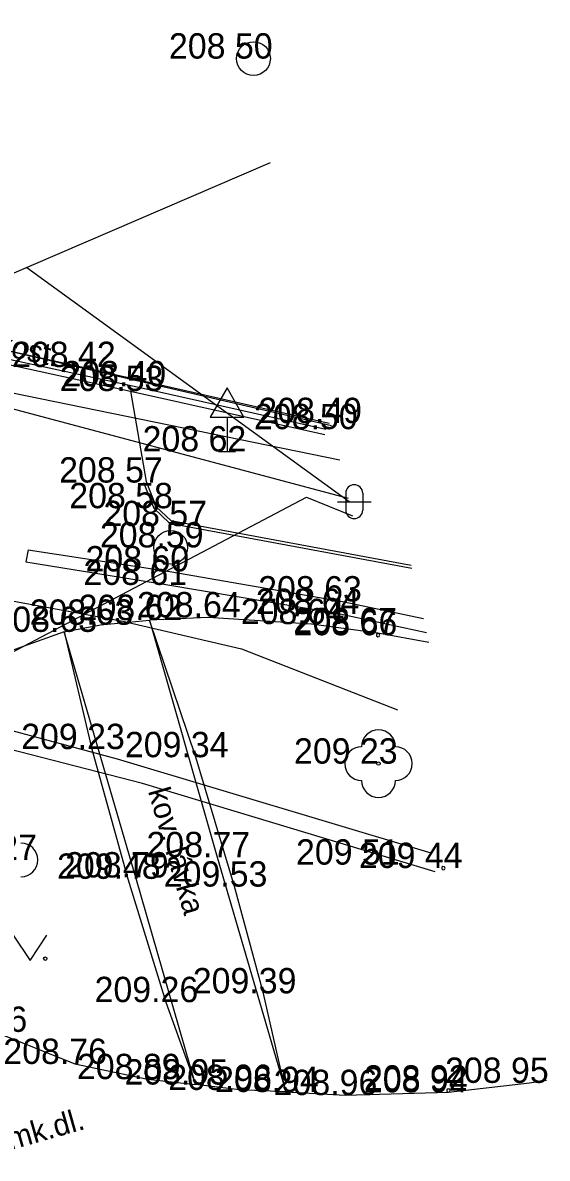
# Model space of a CAD drawing. Extents: x -524633 to -524336, y -1187893 to -1187683.
# Drawn here: x -524498.44 to -524482.91, y -1187763.42 to -1187729.81 of the extents above; entities that cross this region are included whole.
import ezdxf

# ---------------------------------------------------------------- set-up
doc = ezdxf.new("R2010")
doc.units = 0
for name, color, linetype in [('Hranice parcel', 7, 'Continuous'), ('Vrstva 1', 7, 'Continuous'), ('Vrstva 10', 7, 'Continuous'), ('Vrstva 11', 7, 'Continuous'), ('Vrstva 22', 7, 'Continuous'), ('Vrstva 27', 7, 'Continuous'), ('Vrstva 3', 7, 'Continuous'), ('Vrstva 34', 7, 'Continuous'), ('Vrstva 36', 7, 'Continuous'), ('Vrstva 4', 7, 'Continuous'), ('Vrstva 40', 7, 'Continuous'), ('Vrstva 53', 7, 'Continuous'), ('Vrstva 54', 7, 'Continuous'), ('Vrstva 55', 7, 'Continuous'), ('Vrstva 56', 7, 'Continuous')]:
    doc.layers.add(name, color=color, linetype=linetype)

msp = doc.modelspace()

# ---------------------------------------------------------------- linework, layer by layer
at = {"layer": 'Hranice parcel'}
for points in [[(-524488.795, -1187743.895), (-524499.69, -1187740.99), (-524519.03, -1187736.8)], [(-524499.46, -1187739.38), (-524489.297, -1187741.727)], [(-524509.72, -1187754.22), (-524490.04, -1187743.85), (-524488.678, -1187744.401)]]:
    msp.add_lwpolyline(points, dxfattribs=at)
at = {"layer": 'Vrstva 1'}
for p, q in [((-524491.61, -1187730.87), (-524491.61, -1187730.87)), ((-524496.66, -1187740), (-524496.66, -1187740)), ((-524495.25, -1187740.71), (-524495.25, -1187740.71)), ((-524495.14, -1187740.57), (-524495.14, -1187740.57)), ((-524489.37, -1187741.66), (-524489.37, -1187741.66)), ((-524489.47, -1187741.84), (-524489.47, -1187741.84)), ((-524492.39, -1187742.5), (-524492.39, -1187742.5)), ((-524494.86, -1187743.42), (-524494.86, -1187743.42)), ((-524494.56, -1187744.18), (-524494.56, -1187744.18)), ((-524493.55, -1187744.71), (-524493.55, -1187744.71)), ((-524494.06, -1187745.34), (-524494.06, -1187745.34)), ((-524494.08, -1187746.05), (-524494.08, -1187746.05)), ((-524494.14, -1187746.45), (-524494.14, -1187746.45)), ((-524488.97, -1187746.94), (-524488.97, -1187746.94)), ((-524492.96, -1187747.41), (-524492.96, -1187747.41)), ((-524489.04, -1187747.31), (-524489.04, -1187747.31)), ((-524496.14, -1187747.63), (-524496.14, -1187747.63)), ((-524494.69, -1187747.49), (-524494.69, -1187747.49)), ((-524489.89, -1187747.61), (-524489.89, -1187747.61)), ((-524497.21, -1187747.84), (-524497.21, -1187747.84)), ((-524487.93, -1187747.88), (-524487.93, -1187747.88)), ((-524487.92, -1187747.94), (-524487.92, -1187747.94)), ((-524496.39, -1187751.31), (-524496.39, -1187751.31)), ((-524493.32, -1187751.55), (-524493.32, -1187751.55)), ((-524487.91, -1187751.74), (-524487.91, -1187751.74)), ((-524492.68, -1187754.51), (-524492.68, -1187754.51)), ((-524487.85, -1187754.73), (-524487.85, -1187754.73)), ((-524485.99, -1187754.83), (-524485.99, -1187754.83)), ((-524495.33, -1187755.15), (-524495.33, -1187755.15)), ((-524495.09, -1187755.11), (-524495.09, -1187755.11)), ((-524492.17, -1187755.38), (-524492.17, -1187755.38)), ((-524491.31, -1187758.54), (-524491.31, -1187758.54)), ((-524494.2, -1187758.8), (-524494.2, -1187758.8)), ((-524496.9, -1187760.63), (-524496.9, -1187760.63)), ((-524494.74, -1187761.08), (-524494.74, -1187761.08)), ((-524493.33, -1187761.24), (-524493.33, -1187761.24)), ((-524483.44, -1187761.19), (-524483.44, -1187761.19)), ((-524492.02, -1187761.4), (-524492.02, -1187761.4)), ((-524490.65, -1187761.46), (-524490.65, -1187761.46)), ((-524488.9, -1187761.55), (-524488.9, -1187761.55)), ((-524485.84, -1187761.42), (-524485.84, -1187761.42)), ((-524485.84, -1187761.47), (-524485.84, -1187761.47))]:
    msp.add_line(p, q, dxfattribs=at)
at = {"layer": 'Vrstva 10'}
msp.add_lwpolyline([(-524568.939, -1187726.44), (-524568.55, -1187726.47), (-524556.49, -1187728.78), (-524544.45, -1187731.12), (-524530.269, -1187733.86), (-524524.26, -1187734.99), (-524524.27, -1187735.17), (-524524.19, -1187735.27), (-524524.04, -1187735.16), (-524523.98, -1187735.03), (-524514.54, -1187736.79), (-524503.61, -1187738.86), (-524500.18, -1187739.48), (-524495.139, -1187740.57), (-524489.47, -1187741.84)], dxfattribs=at)
at = {"layer": 'Vrstva 11'}
for p, q in [((-524494.09, -1187744.62), (-524486.923, -1187745.953)), ((-524494.054, -1187744.545), (-524486.942, -1187745.868)), ((-524498.28, -1187745.41), (-524494.08, -1187746.05)), ((-524494.08, -1187746.05), (-524488.97, -1187746.94)), ((-524494.14, -1187746.45), (-524489.04, -1187747.31))]:
    msp.add_line(p, q, dxfattribs=at)
for points in [[(-524568.929, -1187726.18), (-524568.43, -1187726.15), (-524556.4, -1187728.45), (-524544.402, -1187730.875), (-524530.223, -1187733.614), (-524514.494, -1187736.544), (-524502.98, -1187738.75), (-524502.949, -1187738.6), (-524496.659, -1187740), (-524489.369, -1187741.66)], [(-524568.949, -1187726.57), (-524568.567, -1187726.599), (-524556.515, -1187728.908), (-524544.475, -1187731.248), (-524530.293, -1187733.988), (-524524.39, -1187735.1), (-524524.34, -1187735.33), (-524524.219, -1187735.389), (-524524.11, -1187735.39), (-524523.92, -1187735.18), (-524514.564, -1187736.918), (-524503.634, -1187738.988), (-524500.26, -1187739.62), (-524495.25, -1187740.71), (-524489.495, -1187741.999)], [(-524495.25, -1187740.71), (-524494.785, -1187743.391), (-524494.492, -1187744.135), (-524494.054, -1187744.545)], [(-524494.86, -1187743.42), (-524494.56, -1187744.18), (-524494.09, -1187744.62)], [(-524498.28, -1187745.41), (-524498.35, -1187745.77), (-524494.14, -1187746.45)], [(-524488.97, -1187746.94), (-524486.582, -1187747.441)], [(-524489.889, -1187747.61), (-524492.96, -1187747.41), (-524494.689, -1187747.49)], [(-524489.04, -1187747.31), (-524486.487, -1187747.854)], [(-524497.209, -1187747.84), (-524496.139, -1187747.63), (-524494.69, -1187747.49)], [(-524494.69, -1187747.49), (-524492.679, -1187754.51), (-524490.649, -1187761.46)], [(-524490.649, -1187761.46), (-524491.31, -1187758.54), (-524492.169, -1187755.38), (-524493.319, -1187751.55), (-524494.69, -1187747.49)], [(-524486.419, -1187748.155), (-524487.93, -1187747.88), (-524489.89, -1187747.61)], [(-524497.209, -1187747.84), (-524499.479, -1187748.65), (-524501.67, -1187749.98), (-524502.959, -1187751.46), (-524503.689, -1187752.93), (-524503.889, -1187754.38), (-524503.539, -1187755.97), (-524502.579, -1187757.37), (-524500.98, -1187758.63), (-524499.26, -1187759.68), (-524496.9, -1187760.63), (-524494.74, -1187761.08), (-524493.329, -1187761.24)], [(-524493.329, -1187761.24), (-524495.09, -1187755.11), (-524497.209, -1187747.84)], [(-524497.209, -1187747.84), (-524496.389, -1187751.31), (-524495.329, -1187755.15), (-524494.2, -1187758.8), (-524493.329, -1187761.24)], [(-524487.87, -1187747.94), (-524487.889, -1187747.901), (-524487.931, -1187747.891), (-524487.965, -1187747.918), (-524487.965, -1187747.962), (-524487.931, -1187747.989), (-524487.889, -1187747.979), (-524487.87, -1187747.94)], [(-524485.94, -1187754.83), (-524485.959, -1187754.791), (-524486.001, -1187754.781), (-524486.035, -1187754.808), (-524486.035, -1187754.852), (-524486.001, -1187754.879), (-524485.959, -1187754.869), (-524485.94, -1187754.83)], [(-524490.649, -1187761.46), (-524492.02, -1187761.4), (-524493.329, -1187761.24)], [(-524488.9, -1187761.55), (-524485.84, -1187761.47), (-524483.44, -1187761.19)], [(-524483.44, -1187761.19), (-524482.941, -1187761.108)], [(-524490.649, -1187761.46), (-524488.9, -1187761.55)], [(-524485.79, -1187761.42), (-524485.809, -1187761.381), (-524485.851, -1187761.371), (-524485.885, -1187761.398), (-524485.885, -1187761.442), (-524485.851, -1187761.469), (-524485.809, -1187761.459), (-524485.79, -1187761.42)]]:
    msp.add_lwpolyline(points, dxfattribs=at)
at = {"layer": 'Vrstva 22'}
msp.add_circle((-524487.91, -1187751.74), 0.05, dxfattribs=at)
for centre, start, end in [((-524487.91, -1187751.24), 0, 180), ((-524488.41, -1187751.74), 90, 270), ((-524487.41, -1187751.74), 270, 90), ((-524487.91, -1187752.24), 180, 0), ((-524498.49, -1187754.59), 270, 90)]:
    msp.add_arc(centre, 0.5, start, end, dxfattribs=at)
at = {"layer": 'Vrstva 27'}
for centre in [(-524491.61, -1187730.87), (-524494.059, -1187745.34)]:
    msp.add_circle(centre, 0.5, dxfattribs=at)
at = {"layer": 'Vrstva 34'}
for p, q in [((-524492.39, -1187741.482), (-524492.39, -1187742.5)), ((-524492.64, -1187742.5), (-524492.14, -1187742.5))]:
    msp.add_line(p, q, dxfattribs=at)
msp.add_lwpolyline([(-524492.89, -1187741.482), (-524491.89, -1187741.482), (-524492.39, -1187740.616)], close=True, dxfattribs=at)
at = {"layer": 'Vrstva 36'}
for p, q in [((-524488.876, -1187743.736), (-524488.876, -1187744.236)), ((-524488.376, -1187743.736), (-524488.376, -1187744.236)), ((-524489.126, -1187743.986), (-524488.126, -1187743.986))]:
    msp.add_line(p, q, dxfattribs=at)
msp.add_lwpolyline([(-524498.72, -1187756.813), (-524498.22, -1187757.563), (-524497.72, -1187756.813)], dxfattribs=at)
msp.add_circle((-524497.771, -1187757.513), 0.05, dxfattribs=at)
for centre, start, end in [((-524488.626, -1187743.736), 0, 180), ((-524488.626, -1187744.236), 180, 0)]:
    msp.add_arc(centre, 0.25, start, end, dxfattribs=at)
at = {"layer": 'Vrstva 53'}
msp.add_lwpolyline([(-524502.2, -1187746.29), (-524495.474, -1187747.52), (-524491.964, -1187748.344), (-524487.346, -1187750.145)], dxfattribs=at)
at = {"layer": 'Vrstva 54'}
msp.add_lwpolyline([(-524489.058, -1187742.759), (-524499.62, -1187740.6), (-524570.13, -1187727.14), (-524573.74, -1187725.2), (-524583.929, -1187713.264)], dxfattribs=at)
at = {"layer": 'Vrstva 55'}
msp.add_line((-524498.317, -1187737.05), (-524488.775, -1187743.982), dxfattribs=at)
msp.add_lwpolyline([(-524537.22, -1187752.94), (-524523.66, -1187747.21), (-524498.97, -1187737.33), (-524491.101, -1187733.95)], dxfattribs=at)
at = {"layer": 'Vrstva 56'}
for points in [[(-524486.234, -1187754.942), (-524494.89, -1187752.33), (-524513.49, -1187747.54), (-524523.96, -1187745.08), (-524532.11, -1187744.84), (-524535.49, -1187743.34), (-524548.39, -1187738.5), (-524555.17, -1187734.62), (-524566.71, -1187730.68), (-524586.54, -1187727.18)], [(-524528.07, -1187743.79), (-524527.33, -1187743.84), (-524523.37, -1187744.09), (-524513.18, -1187746.88), (-524495.64, -1187751.6), (-524486.364, -1187754.379)]]:
    msp.add_lwpolyline(points, dxfattribs=at)

# ---------------------------------------------------------------- texts
at = {"layer": 'Vrstva 3'}
for s, p in [('208 50 ', (-524494.11, -1187730.87)), ('208.40', (-524497.264, -1187740.57)), ('208.49', (-524491.464, -1187741.66)), ('208 58 ', (-524497.06, -1187744.18)), ('208 60 ', (-524496.58, -1187746.05)), ('208.62', (-524496.784, -1187747.49)), ('208 67 ', (-524490.43, -1187747.88)), ('209.34', (-524495.414, -1187751.55)), ('209 23 ', (-524490.41, -1187751.74)), ('209.27', (-524501.084, -1187754.59)), ('209.53', (-524494.264, -1187755.38)), ('209.39', (-524493.404, -1187758.54)), ('208.66', (-524501.371, -1187759.68)), ('208.89', (-524496.834, -1187761.08)), ('208.96', (-524491.011, -1187761.55))]:
    msp.add_text(s, height=0.75, dxfattribs=at).set_placement(p)
at = {"layer": 'Vrstva 4'}
for s, p in [('208.42', (-524498.754, -1187740)), ('208.53', (-524497.344, -1187740.71)), ('208.50', (-524491.594, -1187741.84)), ('208 62 ', (-524494.89, -1187742.5)), ('208 57 ', (-524497.36, -1187743.42)), ('208 57 ', (-524496.05, -1187744.71)), ('208.59', (-524496.154, -1187745.34)), ('208 61 ', (-524496.64, -1187746.45)), ('208 63 ', (-524491.47, -1187746.94)), ('208.64', (-524495.054, -1187747.41)), ('208 64 ', (-524491.54, -1187747.31)), ('208.63', (-524499.304, -1187747.84)), ('208.63', (-524498.234, -1187747.63)), ('208.64', (-524491.984, -1187747.61)), ('208 66 ', (-524490.42, -1187747.94)), ('209.23', (-524498.484, -1187751.31)), ('208.77', (-524494.774, -1187754.51)), ('209 51 ', (-524490.35, -1187754.73)), ('209 44 ', (-524488.49, -1187754.83)), ('209.48', (-524497.424, -1187755.15)), ('208.79', (-524497.184, -1187755.11)), ('209.26', (-524496.311, -1187758.8)), ('208.76', (-524499.011, -1187760.63)), ('208.95', (-524495.425, -1187761.24)), ('208 95 ', (-524485.94, -1187761.19)), ('208.96', (-524494.131, -1187761.4)), ('208.94', (-524492.744, -1187761.46)), ('208 92 ', (-524488.34, -1187761.42)), ('208 94 ', (-524488.34, -1187761.47))]:
    msp.add_text(s, height=0.75, dxfattribs=at).set_placement(p)
at = {"layer": 'Vrstva 40'}
for s, rotation, p in [('kost.', 347.7983, (-524499.242, -1187739.608)), ('kov. lávka', 286.2517, (-524494.734, -1187752.552)), ('zámk.dl.', 15.8468, (-524499.674, -1187763.432))]:
    msp.add_text(s, height=0.65, rotation=rotation, dxfattribs=at).set_placement(p)

doc.saveas('drawing.dxf')
